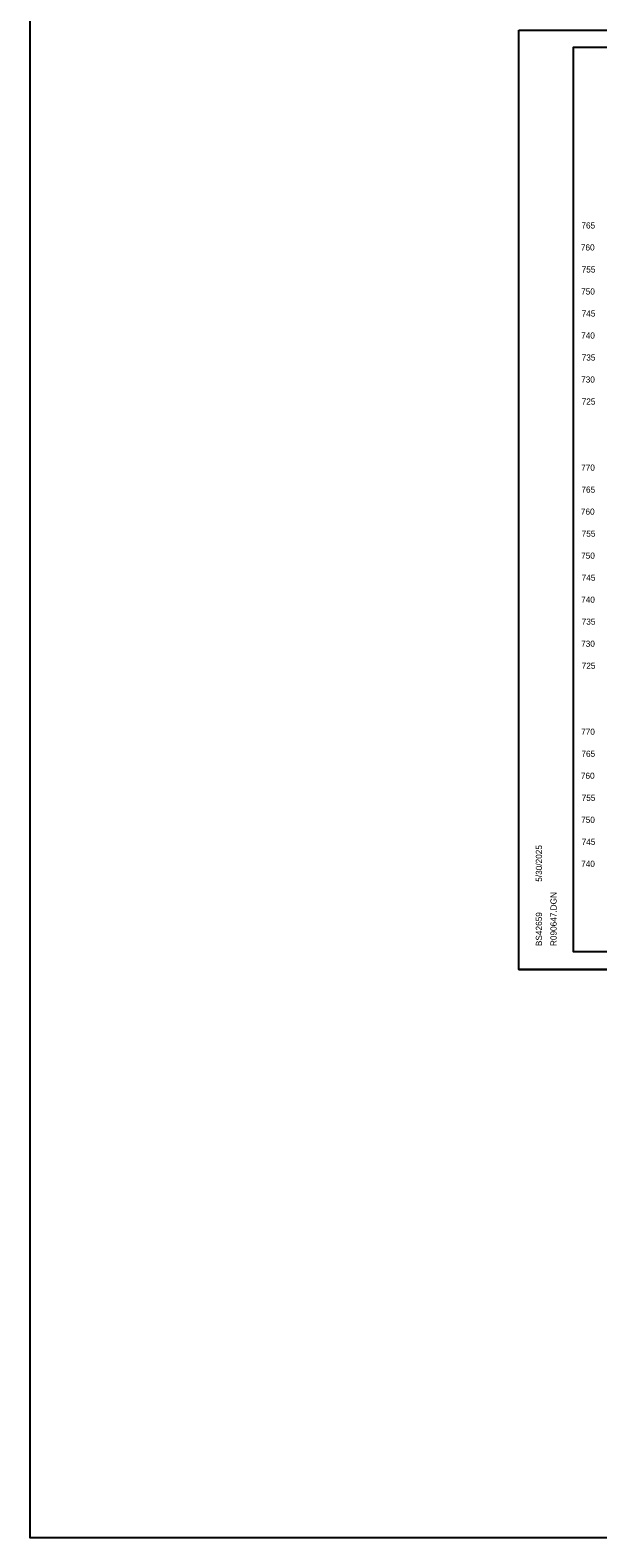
# Model space of a CAD drawing. Extents: x 1202951 to 1376887, y 378065 to 728038.
# Drawn here: x 1376303.2 to 1376432.2, y 378065.4 to 378407.8 of the extents above; entities that cross this region are included whole.
import ezdxf

# ---------------------------------------------------------------- set-up
doc = ezdxf.new("R2010")
doc.units = 0
for name, color, linetype in [('R_Axis Annot', 7, 'Continuous'), ('R_Border', 7, 'Continuous'), ('R_No Plot', 7, 'Continuous')]:
    doc.layers.add(name, color=color, linetype=linetype)

msp = doc.modelspace()

# ---------------------------------------------------------------- linework, layer by layer
at = {"layer": 'R_Border'}
for p, q in [((1376426.67, 378403.94), (1376742.85, 378403.94)), ((1376426.67, 378198.48), (1376426.67, 378403.94)), ((1376426.67, 378198.48), (1376426.67, 378198.48)), ((1376742.85, 378198.48), (1376426.67, 378198.48))]:
    msp.add_line(p, q, dxfattribs=at)
at = {"layer": 'R_No Plot'}
for p, q in [((1376414.27, 378407.83), (1376747.6, 378407.83)), ((1376414.27, 378194.5), (1376747.6, 378194.5))]:
    msp.add_line(p, q, dxfattribs=at)
for points in [[(1376303.24, 380162.87), (1376887.29, 380162.87), (1376887.29, 378065.39), (1376303.24, 378065.39)], [(1376414.26, 378407.83), (1376747.6, 378407.83), (1376747.6, 378194.5), (1376414.26, 378194.5)], [(1376660.59, 378403.94), (1376680.21, 378403.94), (1376680.21, 378394.06), (1376696.32, 378394.06), (1376719.52, 378394.06), (1376719.64, 378365.9), (1376742.85, 378365.9), (1376742.85, 378198.48), (1376426.67, 378198.48), (1376426.67, 378403.94)]]:
    msp.add_lwpolyline(points, close=True, dxfattribs=at)

# ---------------------------------------------------------------- texts
at = {"layer": 'R_Axis Annot'}
for s, p in [('765', (1376428.5, 378362.78)), ('760', (1376428.38, 378357.78)), ('755', (1376428.56, 378352.78)), ('750', (1376428.44, 378347.78)), ('745', (1376428.56, 378342.78)), ('740', (1376428.44, 378337.78)), ('735', (1376428.56, 378332.78)), ('730', (1376428.44, 378327.78)), ('725', (1376428.56, 378322.78)), ('770', (1376428.44, 378307.78)), ('765', (1376428.5, 378302.78)), ('760', (1376428.38, 378297.78)), ('755', (1376428.56, 378292.78)), ('750', (1376428.44, 378287.78)), ('745', (1376428.56, 378282.78)), ('740', (1376428.44, 378277.78)), ('735', (1376428.56, 378272.78)), ('730', (1376428.44, 378267.78)), ('725', (1376428.56, 378262.78)), ('770', (1376428.44, 378247.78)), ('765', (1376428.5, 378242.78)), ('760', (1376428.38, 378237.78)), ('755', (1376428.56, 378232.78)), ('750', (1376428.44, 378227.78)), ('745', (1376428.56, 378222.78)), ('740', (1376428.44, 378217.78))]:
    msp.add_text(s, height=1.4, dxfattribs=at).set_placement(p)
at = {"layer": 'R_Border'}
for s, p in [('5/30/2025', (1376419.54, 378214.41)), ('R090647.DGN', (1376422.86, 378199.8)), ('BS42659', (1376419.54, 378199.8))]:
    msp.add_text(s, height=1.4, rotation=90, dxfattribs=at).set_placement(p)

doc.saveas('drawing.dxf')
